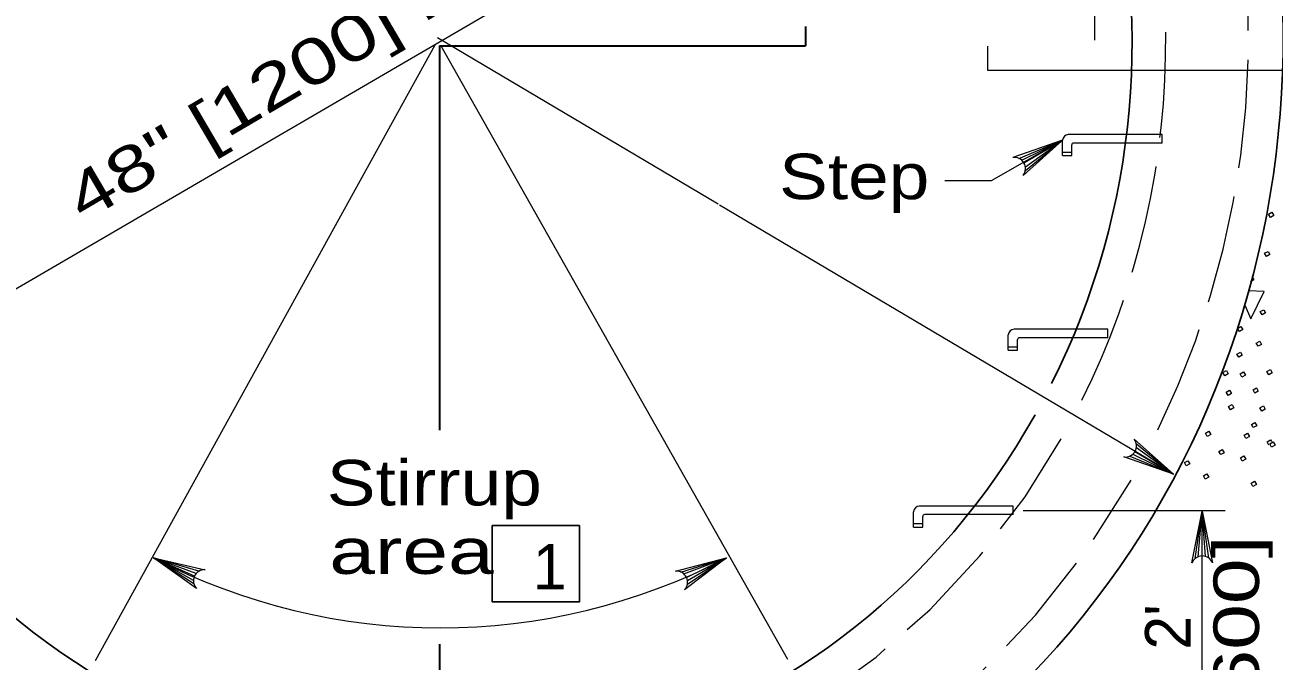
# Model space of a CAD drawing. Extents: x 1170.6 to 1204.6, y 975 to 1019.
# Drawn here: x 1190.902 to 1195.183, y 1000.634 to 1002.815 of the extents above; entities that cross this region are included whole.
import ezdxf
from ezdxf.enums import TextEntityAlignment as Align

# ---------------------------------------------------------------- set-up
doc = ezdxf.new("R2010")
doc.units = 0
doc.header["$LTSCALE"] = 0.062
doc.linetypes.add('LONG_DASHED', pattern=[7.5, 6, -1.5])
doc.linetypes.add('MEDIUM_DASHED', pattern=[4.5, 3, -1.5])
doc.layers.add('1', color=7, linetype='Continuous', lineweight=13)

msp = doc.modelspace()

# ---------------------------------------------------------------- linework, layer by layer
at = {"layer": '1'}
for p, q in [((1194.382, 1003.95808), (1190.26308, 1001.55475)), ((1194.5695, 1002.7625), (1194.5695, 1003.402)), ((1193.278, 1002.2), (1192.31558, 1002.77025)), ((1192.30683, 1002.74575), (1191.14283, 1000.63483)), ((1192.32625, 1002.74542), (1193.51575, 1000.64108)), ((1194.67708, 1002.43892), (1194.47792, 1002.43892)), ((1194.63017, 1002.43892), (1194.47792, 1002.43892)), ((1194.3085, 1002.35758), (1194.45792, 1002.41975)), ((1194.31883, 1002.35075), (1194.45792, 1002.41975)), ((1194.326, 1002.34183), (1194.45792, 1002.41975)), ((1194.33092, 1002.328), (1194.45792, 1002.41975)), ((1194.33092, 1002.31592), (1194.45792, 1002.41975)), ((1194.45792, 1002.36708), (1194.45792, 1002.41975)), ((1194.45792, 1002.36708), (1194.45792, 1002.41975)), ((1194.49, 1002.36708), (1194.49, 1002.40367)), ((1194.49, 1002.36708), (1194.49, 1002.40367)), ((1194.67333, 1002.40975), (1194.49608, 1002.40975)), ((1194.62667, 1002.40975), (1194.49608, 1002.40975)), ((1194.45792, 1002.379), (1194.48983, 1002.379)), ((1194.45792, 1002.379), (1194.48983, 1002.379)), ((1194.45792, 1002.36708), (1194.48983, 1002.36708)), ((1194.45792, 1002.36708), (1194.48983, 1002.36708)), ((1194.83883, 1001.27517), (1193.28233, 1002.19733)), ((1194.27208, 1001.69975), (1194.27208, 1001.75233)), ((1194.27208, 1001.69975), (1194.27208, 1001.75233)), ((1194.505, 1001.7715), (1194.29217, 1001.7715)), ((1194.43942, 1001.7715), (1194.29217, 1001.7715)), ((1194.27208, 1001.71167), (1194.304, 1001.71167)), ((1194.27208, 1001.71167), (1194.304, 1001.71167)), ((1194.27208, 1001.69975), (1194.304, 1001.69975)), ((1194.27208, 1001.69975), (1194.304, 1001.69975)), ((1194.30417, 1001.69975), (1194.30417, 1001.73633)), ((1194.30417, 1001.69975), (1194.30417, 1001.73633)), ((1194.493, 1001.74242), (1194.31033, 1001.74242)), ((1194.42733, 1001.74242), (1194.31033, 1001.74242)), ((1194.71133, 1001.37825), (1194.83883, 1001.27517)), ((1194.71142, 1001.36617), (1194.83883, 1001.27517)), ((1195.16567, 1001.37458), (1195.15958, 1001.38542)), ((1194.68917, 1001.3365), (1194.83883, 1001.27517)), ((1194.69942, 1001.34342), (1194.83883, 1001.27517)), ((1194.70658, 1001.35233), (1194.83883, 1001.27517)), ((1193.94708, 1001.09342), (1193.94708, 1001.14608)), ((1193.94708, 1001.09342), (1193.94708, 1001.14608)), ((1194.1565, 1001.16525), (1193.96717, 1001.16525)), ((1194.1, 1001.16525), (1193.96717, 1001.16525)), ((1194.32283, 1001.14992), (1195.01583, 1001.14992)), ((1194.91242, 1000.98525), (1194.93717, 1001.14742)), ((1194.92283, 1000.99142), (1194.93717, 1001.14742)), ((1194.93717, 1000.99425), (1194.93717, 1001.14742)), ((1194.9485, 1000.99258), (1194.93717, 1001.14742)), ((1194.95958, 1000.98717), (1194.93717, 1001.14742)), ((1194.93717, 1000.2345), (1194.93717, 1001.14742)), ((1193.94708, 1001.10533), (1193.979, 1001.10533)), ((1193.94708, 1001.10533), (1193.979, 1001.10533)), ((1193.97917, 1001.09342), (1193.97917, 1001.13)), ((1193.97917, 1001.09342), (1193.97917, 1001.13)), ((1194.1335, 1001.13608), (1193.98533, 1001.13608)), ((1194.0775, 1001.13608), (1193.98533, 1001.13608)), ((1193.94708, 1001.09342), (1193.979, 1001.09342)), ((1193.94708, 1001.09342), (1193.979, 1001.09342)), ((1191.48267, 1000.92483), (1191.34283, 1000.98742)), ((1191.47933, 1000.9105), (1191.34283, 1000.98742)), ((1191.48067, 1000.8985), (1191.34283, 1000.98742)), ((1191.48875, 1000.93442), (1191.34283, 1000.98742)), ((1191.49825, 1000.94233), (1191.34283, 1000.98742)), ((1193.15017, 1000.93925), (1193.307, 1000.98742)), ((1193.16025, 1000.93258), (1193.307, 1000.98742)), ((1193.16908, 1000.92083), (1193.307, 1000.98742)), ((1193.17242, 1000.89758), (1193.307, 1000.98742)), ((1193.1725, 1000.90992), (1193.307, 1000.98742))]:
    msp.add_line(p, q, dxfattribs=at)
at = {"layer": '1', "lineweight": 35}
for p, q in [((1193.57775, 1002.80967), (1193.57775, 1002.74333)), ((1192.3225, 1002.74333), (1193.57775, 1002.74333)), ((1192.3225, 1002.74333), (1192.3225, 1001.78225)), ((1192.3225, 1002.74333), (1192.3225, 1001.42575)), ((1192.3225, 1000.69217), (1192.3225, 1000.26975))]:
    msp.add_line(p, q, dxfattribs=at)
at = {"layer": '1', "linetype": 'MEDIUM_DASHED'}
for p, q in [((1194.79992, 1002.43892), (1194.63058, 1002.43892)), ((1194.79992, 1002.43892), (1194.68158, 1002.43892)), ((1194.79992, 1002.40975), (1194.79992, 1002.43883)), ((1194.79992, 1002.40975), (1194.79992, 1002.43883)), ((1194.79992, 1002.40975), (1194.62925, 1002.40975)), ((1194.79992, 1002.40975), (1194.6775, 1002.40975)), ((1194.61408, 1001.7715), (1194.44017, 1001.7715)), ((1194.61408, 1001.7715), (1194.50525, 1001.7715)), ((1194.61408, 1001.74242), (1194.61408, 1001.77142)), ((1194.61408, 1001.74242), (1194.61408, 1001.77142)), ((1194.61408, 1001.74242), (1194.43117, 1001.74242)), ((1194.61408, 1001.74242), (1194.49908, 1001.74242)), ((1194.28917, 1001.16525), (1194.1005, 1001.16525)), ((1194.28917, 1001.16525), (1194.15467, 1001.16525)), ((1194.28917, 1001.13608), (1194.28917, 1001.16517)), ((1194.28917, 1001.13608), (1194.28917, 1001.16517)), ((1194.28917, 1001.13608), (1194.08208, 1001.13608)), ((1194.28917, 1001.13608), (1194.13633, 1001.13608))]:
    msp.add_line(p, q, dxfattribs=at)
at = {"layer": '1'}
for points in [[(1194.2025, 1003.9905), (1194.2025, 1004.66792), (1195.30008, 1004.66792), (1195.30008, 1002.65925), (1194.2025, 1002.65925), (1194.2025, 1002.74183)], [(1194.45792, 1002.41975), (1194.21342, 1002.28025), (1194.05442, 1002.28025)], [(1194.3235, 1002.29925), (1194.45792, 1002.41975), (1194.2875, 1002.36017)], [(1195.10717, 1001.95192), (1195.10725, 1001.952), (1195.11358, 1001.94075), (1195.10308, 1001.93475)], [(1195.08367, 1001.85392), (1195.10417, 1001.807), (1195.14975, 1001.90075), (1195.09542, 1001.903)], [(1194.70383, 1001.39492), (1194.83883, 1001.27517), (1194.66817, 1001.33375)], [(1195.15958, 1001.38542), (1195.17142, 1001.39217), (1195.17467, 1001.38642)], [(1194.90183, 1000.97042), (1194.93717, 1001.14742), (1194.97258, 1000.97042)], [(1191.48992, 1000.88275), (1191.34283, 1000.98742), (1191.51883, 1000.94733)], [(1193.13217, 1000.94233), (1193.307, 1000.98742), (1193.16292, 1000.87858)]]:
    msp.add_lwpolyline(points, dxfattribs=at)
for points in [[(1195.16442, 1002.16625), (1195.17625, 1002.173), (1195.18258, 1002.16175), (1195.17075, 1002.155)], [(1195.15092, 1002.032), (1195.16275, 1002.03867), (1195.16908, 1002.0275), (1195.15725, 1002.02075)], [(1195.13617, 1001.832), (1195.148, 1001.83867), (1195.15442, 1001.8275), (1195.1425, 1001.82075)], [(1195.05808, 1001.77475), (1195.07, 1001.78142), (1195.07633, 1001.77025), (1195.0645, 1001.7635)], [(1195.1225, 1001.72442), (1195.13433, 1001.73117), (1195.14067, 1001.71992), (1195.12883, 1001.71317)], [(1195.056, 1001.68675), (1195.06783, 1001.6935), (1195.07417, 1001.68225), (1195.06233, 1001.6755)], [(1195.00833, 1001.6235), (1195.02017, 1001.63025), (1195.0265, 1001.619), (1195.01467, 1001.61225)], [(1195.067, 1001.61908), (1195.07883, 1001.62583), (1195.08525, 1001.61458), (1195.07333, 1001.60783)], [(1195.15892, 1001.62692), (1195.17075, 1001.63367), (1195.17708, 1001.62242), (1195.16525, 1001.61567)], [(1195.01933, 1001.55583), (1195.03117, 1001.56258), (1195.0375, 1001.55133), (1195.02567, 1001.54458)], [(1195.11125, 1001.56367), (1195.12308, 1001.57033), (1195.12942, 1001.55908), (1195.11758, 1001.55242)], [(1195.02775, 1001.50692), (1195.03958, 1001.51367), (1195.04592, 1001.50242), (1195.03408, 1001.49567)], [(1195.13508, 1001.50233), (1195.14692, 1001.50908), (1195.15325, 1001.49783), (1195.14142, 1001.49108)], [(1195.10558, 1001.44558), (1195.1175, 1001.45225), (1195.12383, 1001.44108), (1195.11192, 1001.43433)], [(1194.94808, 1001.41533), (1194.95992, 1001.42208), (1194.96625, 1001.41083), (1194.95442, 1001.40408)], [(1195.0805, 1001.40875), (1195.09233, 1001.41542), (1195.09867, 1001.40417), (1195.08683, 1001.3975)], [(1194.99417, 1001.35308), (1195.006, 1001.35975), (1195.01242, 1001.3485), (1195.0005, 1001.34183)], [(1195.16867, 1001.37858), (1195.1805, 1001.38525), (1195.18683, 1001.374), (1195.175, 1001.36733)], [(1194.87633, 1001.31425), (1194.88817, 1001.321), (1194.8945, 1001.30975), (1194.88267, 1001.303)], [(1195.06808, 1001.33108), (1195.07992, 1001.33783), (1195.08625, 1001.32658), (1195.07442, 1001.31983)], [(1194.94125, 1001.269), (1194.95308, 1001.27567), (1194.95942, 1001.26442), (1194.94758, 1001.25775)], [(1195.10467, 1001.24417), (1195.1165, 1001.25092), (1195.12283, 1001.23967), (1195.111, 1001.23292)]]:
    msp.add_lwpolyline(points, close=True, dxfattribs=at)
at = {"layer": '1', "lineweight": 25}
msp.add_lwpolyline([(1192.50358, 1001.0985), (1192.50358, 1000.83692), (1192.80225, 1000.83692), (1192.80225, 1001.0985)], close=True, dxfattribs=at)
at = {"layer": '1'}
for centre, start, end in [((1194.29316, 1002.32249), 322.65412, 98.48025), ((1194.67362, 1001.37152), 261.82693, 37.65306), ((1194.93724, 1000.9561), 22.08782, 157.91395), ((1191.51744, 1000.90924), 87.96157, 223.7877), ((1193.13472, 1000.90424), 317.84258, 93.6687)]:
    msp.add_arc(centre, 0.0382, start, end, dxfattribs=at)
at = {"layer": '1', "lineweight": 25}
for centre, major_axis, start_param, end_param in [((1192.32696, 1002.75942), (0, 2.50862), 4.2253836, 7.3170107), ((1192.33349, 1002.76462), (0, 3.04986), 0.5380125, 3.4065639), ((1192.33349, 1002.76462), (0, 3.04986), 3.7685949, 5.2606747), ((1192.32696, 1002.75942), (0, 2.50862), 1.0936207, 4.176477)]:
    msp.add_ellipse(centre, major_axis=major_axis, ratio=0.944544, start_param=start_param, end_param=end_param, dxfattribs=at)
at = {"layer": '1', "linetype": 'LONG_DASHED'}
for centre, major_axis, start_param, end_param in [((1192.32486, 1002.77617), (0, 2.93373), 1.1026757, 4.1670365), ((1192.31467, 1002.75942), (0, 2.64426), 1.0870422, 4.1813172), ((1192.32486, 1002.77617), (0, 2.93373), 4.2344755, 5.1344826), ((1192.31467, 1002.75942), (0, 2.64426), 4.2279955, 4.7240422)]:
    msp.add_ellipse(centre, major_axis=major_axis, ratio=0.944544, start_param=start_param, end_param=end_param, dxfattribs=at)
at = {"layer": '1'}
for centre, major_axis, start_param, end_param in [((1194.47842, 1002.41701), (0, 0.02191), 0.0230398, 1.4456919), ((1194.47842, 1002.41701), (0, 0.02191), 0.0230398, 1.4456919), ((1194.49576, 1002.40364), (0, 0.00612), 6.2212346, 7.8497314), ((1194.49576, 1002.40364), (0, 0.00612), 6.2212346, 7.8497314), ((1194.29261, 1001.74964), (0, 0.02191), 0.0230398, 1.4456919), ((1194.29261, 1001.74964), (0, 0.02191), 0.0230398, 1.4456919), ((1194.30995, 1001.73627), (0, 0.00612), 6.2212346, 7.8497314), ((1194.30995, 1001.73627), (0, 0.00612), 6.2212346, 7.8497314), ((1193.96764, 1001.14332), (0, 0.02191), 0.0230398, 1.4456919), ((1193.96764, 1001.14332), (0, 0.02191), 0.0230398, 1.4456919), ((1193.98498, 1001.12996), (0, 0.00612), 6.2212346, 7.8497314), ((1193.98498, 1001.12996), (0, 0.00612), 6.2212346, 7.8497314), ((1192.32492, 1003.12257), (0, -2.37487), 5.8300282, 6.7363424)]:
    msp.add_ellipse(centre, major_axis=major_axis, ratio=0.944544, start_param=start_param, end_param=end_param, dxfattribs=at)

# ---------------------------------------------------------------- texts
at = {"layer": '1', "width": 1.35}
msp.add_text('48" [1200] min. diameter', height=0.156, rotation=30.407, dxfattribs=at).set_placement((1191.10175, 1002.137))
at = {"layer": '1', "width": 1.2}
msp.add_text('Step', height=0.156, dxfattribs=at).set_placement((1193.48675, 1002.21758))
at = {"layer": '1'}
for s, width, p in [('Stirrup', 1.2, (1192.30496, 1001.16758)), ('area  ', 1.35, (1192.305, 1000.93292))]:
    msp.add_text(s, height=0.156, dxfattribs=dict(at, width=width)).set_placement(p, align=Align.CENTER)
msp.add_text('1', height=0.156, dxfattribs=at).set_placement((1192.64242, 1000.87942))
at = {"layer": '1', "width": 1.35}
msp.add_text('[600]', height=0.156, rotation=90, dxfattribs=at).set_placement((1195.13175, 1000.75104), align=Align.CENTER)
at = {"layer": '1'}
msp.add_text("2'", height=0.156, rotation=90, dxfattribs=at).set_placement((1194.89708, 1000.751), align=Align.CENTER)

doc.saveas('drawing.dxf')
